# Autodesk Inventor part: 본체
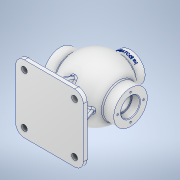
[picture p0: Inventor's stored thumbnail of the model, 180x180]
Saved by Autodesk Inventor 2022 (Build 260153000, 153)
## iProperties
Created: 2024-04
Part Number: 본체
Material: 알루미늄 6061
Document SubType Name: Modeling
Designer: user
Density: 2.7 g/cm^3
Appearance: 알루미늄 - 평지
Mass: 1528.11 g
Surface Area: 1173.66 cm^2
Volume: 565.967 cm^3
Author: user
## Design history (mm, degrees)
sketch "스케치1"
  geometry: L1 (-91, 0)-(91, 0) reference; L2 (0, -10.8)-(0, 64.8) reference; L3 (-44.215, 31)-(-65, 31); L4 (44.215, 31)-(65, 31); L5 (-65, 31)-(-65, 0); L6 (65, 31)-(65, 0); L7 (-44, 0)-(-65, 0); L8 (44, 0)-(65, 0); A1 r 54 centre (0, 0) between (44.215, 31) and (-44.215, 31); A2 r 44 centre (0, 0) between (44, 0) and (-44, 0); 1 further point
  constraints: 12 end point, 4 point on circle, 4 point on line, 3 collinear, 2 centre point, 2 coincident, 2 horizontal, 2 perpendicular
  dimensions: "d0" = 54 radius of A1; "d1" = 130 distance of L4.end L3.end; "d2" = 62 diameter of L3.end L1; "d3" = 62 diameter of L4.end L1; "d4" = 44 radius of A2
revolve "회전1" sketch "스케치1" stored, may be unused: angle "d5" = 90 deg
sketch "스케치2"
  geometry: C1 r 17.5 at (0, 0); 1 further point
  constraints: 1 centre point, 1 coincident
  dimensions: "d6" = 35 diameter of C1
extrude "돌출1" cut sketch "스케치2" distance "d7" = 15; taper "d8" = 0 deg
sketch "스케치3"
  geometry: C1 r 15 at (0, 0); 1 further point
  constraints: 1 centre point, 1 coincident
  dimensions: "d9" = 30 diameter of C1
extrude "돌출2" cut sketch "스케치3" extent not by distance; stored distance "d10" = 0; taper "d11" = 0 deg
fillet "모깎기1" dims "d12" = 0.6
node "작업 평면1"
sketch "스케치4"
  geometry: C1 r 27 at (0, 0); 1 further point
  constraints: 1 centre point, 1 coincident
  dimensions: "d14" = 54 diameter of C1
extrude "돌출3" join sketch "스케치4" stored distance "d15" = 10; taper "d16" = 0 deg
sketch "스케치5"
  geometry: C1 r 13 at (0, 0); 1 further point
  constraints: 1 centre point, 1 coincident
  dimensions: "d17" = 26 diameter of C1
extrude "돌출4" cut sketch "스케치5" stored distance "d18" = 10; taper "d19" = 0 deg
node "작업 평면2"
sketch "스케치6"
  geometry: L1 (62.5, -62.5)-(-62.5, -62.5); L2 (-62.5, -62.5)-(-62.5, 62.5); L3 (-62.5, 62.5)-(62.5, 62.5); L4 (62.5, 62.5)-(62.5, -62.5); L5 (62.5, -62.5)-(-62.5, 62.5); L6 (-62.5, -62.5)-(62.5, 62.5); 1 further point
  constraints: 12 end point, 2 midpoint, 2 parallel, 1 horizontal, 1 perpendicular
  dimensions: "d21" = 125 distance of L2.end L3.end; "d22" = 125 distance of L1.end L2.end
extrude "돌출5" join sketch "스케치6" distance "d23" = 10; taper "d24" = 0 deg
sketch "스케치7"
  geometry: L1 (-91, 85)-(91, 85) reference; L2 (-62.5, 75)-(62.5, 75) reference; L3 (50.5, 75)-(35.692, 34.314); L4 (62.5, 85)-(62.5, 75) reference; L5 (35.692, 34.314)-(0, 52.046); L6 (0, 52.046)-(0, 75); L7 (50.5, 75)-(0, 75); A1 r 54 centre (0, 0) between (-44.215, -31) and (-44.215, 31) reference; 1 further point
  constraints: 8 end point, 1 collinear, 1 midpoint, 1 point on line
  dimensions: "d25" = 85 distance from line of L1 point (0, 0) (derived); "d26" = 12 distance from line of L4 L3.start; "d27" = 20 deg angle of L4 L3
extrude "돌출6" join sketch "스케치7" stored distance "d28" = 8; taper "d29" = 0 deg
node "작업 평면3"
sketch "스케치8"
  geometry: L1 (62.5, 75)-(-62.5, 75) reference; L2 (-50.5, 75)-(-36.752, 37.227); L3 (-62.5, 85)-(-62.5, 75) reference; L4 (-36.752, 37.227)-(0, 52.688); L5 (0, 52.688)-(0, 75); L6 (-50.5, 75)-(0, 75); 1 further point
  constraints: 8 end point, 1 collinear, 1 midpoint, 1 point on line
  dimensions: "d31" = 12 distance from line of L3 L2.start; "d32" = 20 deg angle of L3 L2
extrude "돌출7" join sketch "스케치8" stored distance "d33" = 8; taper "d34" = 0 deg
fillet "모깎기2" dims "d35" = 16
fillet "모깎기3" dims "d36" = 3
fillet "모깎기4" dims "d37" = 3
fillet "모깎기5" dims "d38" = 3
sketch "스케치9"
  geometry: C1 r 5.5 at (46.5, -46.5); A1 r 16 centre (46.5, -46.5) between (46.5, -62.5) and (62.5, -46.5) reference; 1 further point
  constraints: 1 centre point, 1 coincident
  dimensions: "d39" = 11 diameter of C1
extrude "돌출8" cut sketch "스케치9" extent not by distance; stored distance "d40" = 0; taper "d41" = 0 deg
sketch "스케치10" dims "d42" = 48
  geometry: 3 further points
  constraints: 1 coincident, 1 horizontal alignment, 2 other
hole "구멍1" sketch "스케치10" at (-24, 0) diameter "d43" = 3.242; stored, may be unused: countersink angle "d47" = 90 deg, drill point angle "d49" = 118 deg; dims "d44" = 12, "d45" = 12, "d46" = 5, "d48" = 15
sketch "스케치11" dims "d53" = 40
  geometry: 3 further points
  constraints: 1 coincident, 1 vertical alignment, 2 other
hole "구멍2" sketch "스케치11" at (0, -20) diameter "d54" = 3.242; stored, may be unused: countersink angle "d58" = 90 deg, drill point angle "d60" = 118 deg; dims "d55" = 9, "d56" = 4, "d57" = 2, "d59" = 11
chamfer "모따기1" distance "d64" = 1; stored, may be unused: second distance "d65" = 2, angle "d66" = 45 deg
node "작업 평면4"
sketch "스케치12"
  geometry: L1 (27, -65)-(-27, -65) reference; 2 further points
  constraints: 1 vertical alignment, 1 other
  dimensions: "d68" = 9 distance from line of L1 point (0, -56)
feature "엠보싱1" sketch "스케치12" dims "d69" = 0.5, "d70" = 0
node "솔리드1"
mirror "미러1"
mirror "미러2"
mirror "미러3"
mirror "미러4"
mirror "미러5"
pattern_circular "원형 패턴1" dims angle "d51" = 360 deg
mirror "미러6"
pattern_circular "원형 패턴2" dims angle "d62" = 360 deg
feature "A9D066F2-1C7D-4E18-AEED-F7BC21143FA4" dims "d43" = 3.242, "d44" = 12, "d45" = 12, "d46" = 5, "d47" = 90 deg, "d48" = 15, "d49" = 118 deg
other parameters: "d13" = -65, "d20" = 85, "d30" = 0, "d67" = 84.5
